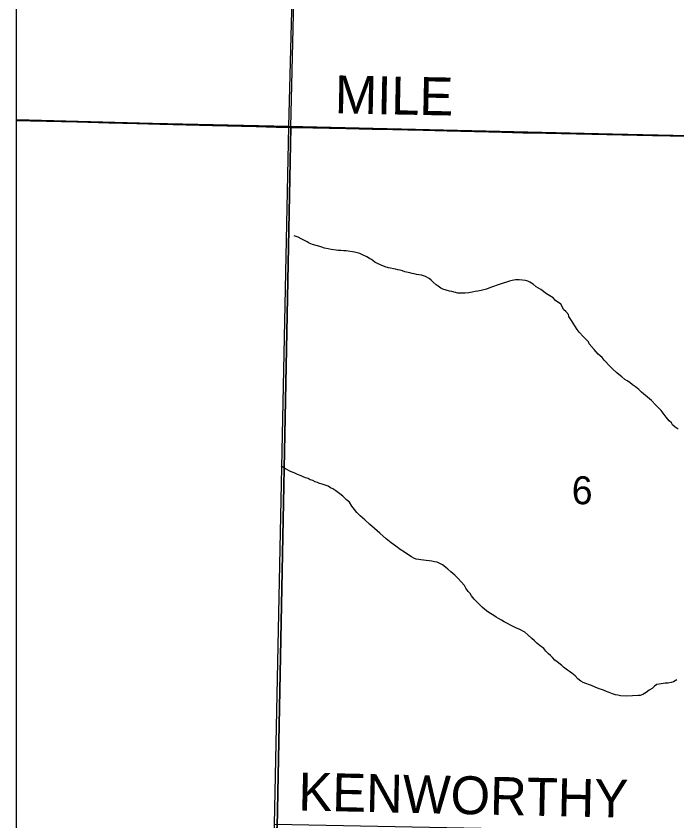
# Model space of a CAD drawing. Extents: x 0 to 34, y 0 to 22.
# Drawn here: x 23.9 to 24.395, y 14.846 to 15.449 of the extents above; entities that cross this region are included whole.
import ezdxf

# ---------------------------------------------------------------- set-up
doc = ezdxf.new("R2010")
doc.units = 0
for name, color, linetype in [('GM_X_County_Road', 7, 'Continuous'), ('GM_X_County_Road_Text', 7, 'Continuous'), ('GM_X_Minor_River', 7, 'Continuous'), ('GM_X_Section', 7, 'Continuous'), ('GM_X_Section_Text', 7, 'Continuous'), ('GM_X_Township', 7, 'Continuous'), ('GM_X_Township_Road_Text', 7, 'Continuous'), ('GM_X_Unincorporated', 7, 'Continuous'), ('SC_Scratch1', 7, 'Continuous'), ('SH_Border', 7, 'Continuous'), ('SH_Cut_Line', 7, 'Continuous')]:
    doc.layers.add(name, color=color, linetype=linetype)

msp = doc.modelspace()

# ---------------------------------------------------------------- linework, layer by layer
at = {"layer": 'GM_X_County_Road'}
for points in [[(23.89999, 15.37102), (23.91081, 15.37072), (23.92603, 15.37038), (23.9459, 15.36979), (23.96951, 15.36928), (23.99032, 15.36871), (24.0077, 15.36827), (24.04714, 15.36724), (24.07975, 15.3664), (24.09466, 15.36604), (24.10578, 15.36574)], [(24.10578, 15.36574), (24.10987, 15.36563), (24.1344, 15.36509), (24.14713, 15.36483), (24.16669, 15.36442), (24.18222, 15.36414), (24.1934, 15.36391), (24.20488, 15.36364), (24.21357, 15.36341), (24.22289, 15.36315), (24.23313, 15.36293), (24.24337, 15.36272), (24.25393, 15.36243), (24.26386, 15.36218), (24.27939, 15.36176), (24.29678, 15.36131), (24.31976, 15.36082), (24.34243, 15.36033), (24.3766, 15.35962), (24.40268, 15.3591)]]:
    msp.add_lwpolyline(points, dxfattribs=at)
at = {"layer": 'GM_X_Minor_River'}
for points in [[(24.18933, 15.25831), (24.18763, 15.25875), (24.18575, 15.25919), (24.18405, 15.25963), (24.18254, 15.25988), (24.18027, 15.26033), (24.17876, 15.26058), (24.17631, 15.26123), (24.17331, 15.26248), (24.1707, 15.26371), (24.16865, 15.26492), (24.16624, 15.26671), (24.16475, 15.26753), (24.1627, 15.26874), (24.15933, 15.27037), (24.15746, 15.2712), (24.15332, 15.27229), (24.14727, 15.27326), (24.14537, 15.27333), (24.14309, 15.2736), (24.1412, 15.27367), (24.13968, 15.27391), (24.1359, 15.27442), (24.13382, 15.27487), (24.13099, 15.27535), (24.12892, 15.27599), (24.12741, 15.27643), (24.12459, 15.27729), (24.12196, 15.27814), (24.11953, 15.27917), (24.11803, 15.27998), (24.11541, 15.28121), (24.11336, 15.28224), (24.11131, 15.28345), (24.10981, 15.28407), (24.10831, 15.2845)], [(24.39582, 15.13977), (24.39359, 15.14118), (24.39156, 15.14296), (24.39085, 15.1445), (24.38901, 15.14609), (24.38682, 15.14882), (24.38445, 15.15175), (24.383, 15.15371), (24.38135, 15.15547), (24.37915, 15.15783), (24.37585, 15.16117), (24.36847, 15.16751), (24.36644, 15.16948), (24.36385, 15.17147), (24.36163, 15.17307), (24.35959, 15.17466), (24.35755, 15.17606), (24.35587, 15.17707), (24.35366, 15.17886), (24.35125, 15.18065), (24.34977, 15.18203), (24.34682, 15.18461), (24.34499, 15.18657), (24.34041, 15.19148), (24.33877, 15.19344), (24.33601, 15.19601), (24.3329, 15.19953), (24.32905, 15.20366), (24.32873, 15.20519), (24.32486, 15.20893), (24.32157, 15.21247), (24.32011, 15.21442), (24.3185, 15.21713), (24.31598, 15.22121), (24.31399, 15.22413), (24.31367, 15.22566), (24.31165, 15.22782), (24.31018, 15.22921), (24.30804, 15.23327), (24.30396, 15.23607), (24.30231, 15.23803), (24.29729, 15.24106), (24.29284, 15.24425), (24.28949, 15.24646), (24.28727, 15.24824), (24.28467, 15.24986), (24.28317, 15.25048), (24.28148, 15.25111), (24.27921, 15.25138), (24.27675, 15.25165), (24.27389, 15.25156), (24.27159, 15.25107), (24.26948, 15.25058), (24.26718, 15.2499), (24.26487, 15.24903), (24.26256, 15.24835), (24.26025, 15.24748), (24.25755, 15.24662), (24.25524, 15.24575), (24.25235, 15.24471), (24.25024, 15.24403), (24.24832, 15.24352), (24.24583, 15.24304), (24.24373, 15.24273), (24.24143, 15.24224), (24.23913, 15.24175), (24.23628, 15.24166), (24.23418, 15.24155), (24.23076, 15.24167), (24.22643, 15.24277), (24.22454, 15.24321), (24.21965, 15.24471), (24.21815, 15.24533), (24.21612, 15.24693), (24.21463, 15.24793), (24.21223, 15.24991), (24.21076, 15.25129), (24.20928, 15.25248), (24.20667, 15.2541), (24.20517, 15.25453), (24.20347, 15.25497), (24.20158, 15.25541), (24.19988, 15.25566), (24.19819, 15.2561), (24.19648, 15.25635), (24.19479, 15.25679), (24.19102, 15.25768), (24.18933, 15.25831)], [(24.13941, 15.09362), (24.13718, 15.09503), (24.1355, 15.09584), (24.13364, 15.09705), (24.13082, 15.0981), (24.12913, 15.09854), (24.12725, 15.09917), (24.12575, 15.09979), (24.12406, 15.10042), (24.12219, 15.10125), (24.12031, 15.10188), (24.11882, 15.1027), (24.11675, 15.10334), (24.11506, 15.10416), (24.11338, 15.10479), (24.11075, 15.10583), (24.10813, 15.10706), (24.10663, 15.10749), (24.10494, 15.10831), (24.10327, 15.10932), (24.10178, 15.11013), (24.09861, 15.11195)], [(24.37642, 14.94552), (24.37409, 14.94427), (24.37194, 14.94263), (24.36942, 14.94101), (24.3673, 14.94033), (24.36578, 14.94038), (24.3574, 14.93991), (24.35265, 14.94008), (24.35058, 14.94053), (24.34887, 14.94078), (24.34662, 14.94162), (24.34419, 14.94265), (24.34268, 14.94309), (24.33987, 14.94433), (24.33837, 14.94476), (24.33668, 14.94539), (24.33368, 14.94663), (24.33086, 14.94768), (24.32936, 14.9483), (24.32674, 14.94934), (24.32467, 14.94999), (24.3228, 14.951), (24.32078, 14.95278), (24.31857, 14.95495), (24.31618, 14.95712), (24.31451, 14.95832), (24.31283, 14.95933), (24.31005, 14.96152), (24.30858, 14.96271), (24.30525, 14.96548), (24.3034, 14.96688), (24.30175, 14.96864), (24.30009, 14.97022), (24.29862, 14.9716), (24.2966, 14.97357), (24.29515, 14.97552), (24.29237, 14.97752), (24.28996, 14.97951), (24.28813, 14.98128), (24.2861, 14.98306), (24.28315, 14.98582), (24.28093, 14.98761), (24.2772, 14.98964), (24.27421, 14.99107), (24.27234, 14.9919), (24.27028, 14.99292), (24.26804, 14.99414), (24.26562, 14.99555), (24.26338, 14.99677), (24.26133, 14.99798), (24.25947, 14.999), (24.2578, 15.0002), (24.25538, 15.00161), (24.25334, 15.00301), (24.25111, 15.00461), (24.24908, 15.00639), (24.24724, 15.00816), (24.24522, 15.01013), (24.24302, 15.01249), (24.24102, 15.01503), (24.23994, 15.01659), (24.23866, 15.01815), (24.23685, 15.02069), (24.23578, 15.02262), (24.23321, 15.02537), (24.23102, 15.02792), (24.22845, 15.03048), (24.22568, 15.03285), (24.22328, 15.03503), (24.22162, 15.03642), (24.21921, 15.03821), (24.21678, 15.03943), (24.21529, 15.04006), (24.21321, 15.04051), (24.21132, 15.04095), (24.20924, 15.04122), (24.20697, 15.04149), (24.20319, 15.042), (24.20167, 15.04224), (24.19959, 15.0425), (24.1979, 15.04313), (24.19604, 15.04415), (24.19418, 15.04535), (24.19083, 15.04756), (24.18768, 15.04976), (24.18434, 15.05216), (24.18081, 15.05456), (24.17712, 15.05773), (24.17232, 15.06188), (24.16827, 15.06544), (24.16458, 15.06861), (24.16108, 15.07177), (24.15776, 15.07474), (24.15519, 15.0773), (24.15337, 15.07964), (24.15136, 15.08199), (24.14957, 15.0851), (24.14754, 15.08688), (24.14459, 15.08964), (24.14237, 15.09143), (24.13941, 15.09362)], [(24.3949, 14.95209), (24.39238, 14.95066), (24.39046, 14.94997), (24.38835, 14.94966), (24.38607, 14.94955), (24.38454, 14.94941), (24.38148, 14.94876), (24.37975, 14.94844), (24.378, 14.94717), (24.37642, 14.94552)]]:
    msp.add_lwpolyline(points, dxfattribs=at)
at = {"layer": 'GM_X_Section'}
for points in [[(24.5908, 15.86163), (24.51511, 15.35675), (24.1043, 15.36652), (24.11719, 15.86705)], [(24.1043, 15.36652), (24.51511, 15.35675), (24.55374, 15.35601), (24.54471, 14.83493), (24.09352, 14.84359)]]:
    msp.add_lwpolyline(points, close=True, dxfattribs=at)
at = {"layer": 'GM_X_Township'}
msp.add_lwpolyline([(24.43759, 15.35857), (24.33545, 15.36086), (24.23455, 15.36312), (24.14939, 15.36503), (24.10567, 15.36601), (24.11364, 15.70392)], dxfattribs=at)
at = {"layer": 'GM_X_Unincorporated'}
for points in [[(23.89999, 15.87296), (23.89999, 15.37101), (24.1043, 15.36652), (24.11719, 15.86705)], [(23.89999, 15.37101), (23.89999, 14.82591), (24.09215, 14.81047), (24.09352, 14.84359), (24.1043, 15.36652)]]:
    msp.add_lwpolyline(points, close=True, dxfattribs=at)
at = {"layer": 'SC_Scratch1'}
for points in [[(23.89999, 18.40604), (23.89999, 15.37146), (23.90968, 15.37123), (24.02912, 15.36781), (24.10567, 15.36601), (24.11364, 15.70392)], [(24.08197, 14.12959), (24.08615, 14.33912), (24.08629, 14.34636), (24.08779, 14.44256), (24.091, 14.64839), (24.0935, 14.80854), (24.09368, 14.82566), (24.09373, 14.8326), (24.09377, 14.83387), (24.09381, 14.83524), (24.09388, 14.83632), (24.09396, 14.83744), (24.0941, 14.83846), (24.0942, 14.839), (24.09437, 14.83958), (24.09457, 14.84016), (24.09484, 14.84078), (24.09544, 14.84169), (24.10567, 15.36601), (24.02912, 15.36781), (23.90968, 15.37123), (23.89999, 15.37146), (23.89999, 13.43613)], [(24.43759, 15.35857), (24.33545, 15.36086), (24.23455, 15.36312), (24.14939, 15.36503), (24.10567, 15.36601), (24.09544, 14.84169), (24.09484, 14.84078), (24.09457, 14.84016), (24.09437, 14.83958), (24.0942, 14.839), (24.0941, 14.83846), (24.09396, 14.83744), (24.09388, 14.83632), (24.09381, 14.83524), (24.09377, 14.83387), (24.09373, 14.8326), (24.09368, 14.82566), (24.0935, 14.80854), (24.091, 14.64839), (24.08779, 14.44256), (24.08629, 14.34636), (24.08615, 14.33912), (24.08197, 14.12959)]]:
    msp.add_lwpolyline(points, dxfattribs=at)
at = {"layer": 'SH_Border'}
msp.add_lwpolyline([(23.89999, 20.23613), (23.89999, 13.43613), (30.69999, 13.43613), (30.69999, 20.23613)], close=True, dxfattribs=at)
at = {"layer": 'SH_Cut_Line'}
msp.add_lwpolyline([(23.89999, 20.23613), (23.89999, 13.43613), (30.0382, 13.43613)], dxfattribs=at)

# ---------------------------------------------------------------- texts
at = {"layer": 'GM_X_County_Road_Text'}
msp.add_text('MILE', height=0.028409, rotation=358.883, dxfattribs=at).set_placement((24.13852, 15.37632))
at = {"layer": 'GM_X_Section_Text'}
msp.add_text('6', height=0.02093, rotation=0.00001, dxfattribs=at).set_placement((24.31613, 15.08353))
at = {"layer": 'GM_X_Township_Road_Text'}
msp.add_text('KENWORTHY', height=0.028409, rotation=358.71975, dxfattribs=at).set_placement((24.11117, 14.85426))

doc.saveas('drawing.dxf')
